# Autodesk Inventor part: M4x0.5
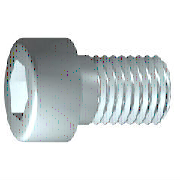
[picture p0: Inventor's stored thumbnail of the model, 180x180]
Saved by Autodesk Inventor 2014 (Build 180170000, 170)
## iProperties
IsCustomPart: 1
Company: 한국ATC센터
Created: 2009-02
Part Number: M4x0.5
Material: Steel, Mild
Description: 6각머리 태핑 나사
Document SubType Name: Modeling
Standard: KS B 1003
Designer: KYOUNG IL JANG
Standards Organization: KS
Language: ko-KR
Size Designation: M 4 x 12
Categories: <MemberInstance><Categories><Category DisplayName="조임쇠" InternalName="e4da775c-781d-43d5-af7c-5136215cf5a6" Mnemonic="FSTN"><Category DisplayName="볼트" InternalN
Density: 1 g/cm^3
Appearance: Steel
Author: KYOUNG IL JANG
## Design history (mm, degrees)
revolve "본체" stored, may be unused: angle "d10" = 90 deg
sketch "스케치2"
  geometry: L1 (0, -4.9)-(0, 4.9) reference; L2 (-4.9, 0)-(4.9, 0) reference; L3 (1.732, 0)-(0.866, -1.5); L4 (0.866, -1.5)-(-0.866, -1.5); L5 (-0.866, -1.5)-(-1.732, 0); L6 (-1.732, 0)-(-0.866, 1.5); L7 (-0.866, 1.5)-(0.866, 1.5); L8 (0.866, 1.5)-(1.732, 0); 2 further points
  constraints: 12 end point, 1 coincident, 1 horizontal alignment, 1 point on line, 12 other
extrude "슬롯" join sketch "스케치2" stored distance "d11" = 10; taper "d12" = 0 deg
workplane "Work Plane1"
fillet "Fillet2" dims "d30" = 0.1 (= R)
body "Solid1"
fillet "모깎기1" dims "d17" = 0.4 (= RR)
feature "스레드" dims "d13" = 10.25 (= GEL), "d14" = 0
chamfer "모따기1" distance "d15" = 0.42941 (= -0.5 x SPD + 0.5 x GD); stored, may be unused: second distance "d16" = 0.42941 (= GUL), angle "d27" = 45 deg
sketch "스케치1"
  geometry: L1 (-1, 0)-(12, 0); L2 (12, 0)-(12, 2); L3 (12, 2)-(1.75, 2); L4 (1.75, 2)-(1.32, 2); L5 (1.32, 2)-(0, 2); L6 (0, 2)-(0, 3.5); L7 (0, 3.5)-(-4, 3.5); L8 (-4, 3.5)-(-4, 1.732); L9 (-4, 1.732)-(-2, 1.732); L10 (-2, 1.732)-(-1, 0); L11 (-7.2, 0)-(15.2, 0) reference; L12 (0, -0.7)-(0, 4.2) reference; L13 (1.75, 2)-(0, 2)
  constraints: 22 end point, 6 parallel, 2 collinear, 2 perpendicular, 1 horizontal, 1 point on line
  dimensions: "d1" = 10.25 distance from line of L3.end L2 (= GEL); "d2" = 0.42952 distance of L4.end L3.end (computed from GAL); "d3" = 4 distance between parallel lines of L8 L6 (= KOH); "d4" = 2 distance of L8.end L9.end (= INTI); "d5" = 60 deg angle of L10 L1; "d6" = 4 diameter of L3 L1 (= GD); "d7" = 4 diameter of L5 L1 (= BDM); "d8" = 3.4641 diameter of L9 L1 (= 1.1547 x SW); "d9" = 7 diameter of L7 L1 (= KOD); "d26" = 12 distance between parallel lines of L12 L2 (= NLG)
other parameters: "GD" = 4 (= NND) [user parameter; used in 2 equation terms], "NLG" = 12 [user parameter; used in 1 equation term], "GEL" = 10.25 [user parameter; used in 2 equation terms], "KOD" = 7 [user parameter; used in 1 equation term], "KOH" = 4 [user parameter; used in 1 equation term], "INTI" = 2 [user parameter; used in 1 equation term], "GAL" = 0.42941 (= 0.61345 x PTC) [user parameter; used in 1 equation term], "GUL" = 0.42941 (= 0.61345 x PTC) [user parameter; used in 1 equation term], "BDM" = 4 (= NND) [user parameter; used in 1 equation term], "SW" = 3 [user parameter; used in 2 equation terms], "RR" = 0.4 [user parameter; used in 1 equation term], "SPD" = 3.14117 (= NND - 1.2269 x PTC) [user parameter; used in 1 equation term], "d19" = 0, "d28" = 0, "d29" = 0, "R" = 0.1 [user parameter; used in 1 equation term], "PHH" = 0.2 [user parameter], "GD1" = 3.14117 (= THREADDIA - 1.2269 x PTC) [user parameter], "THREADDIA" = 4 [user parameter; used in 1 equation term], "FAWI" = 45 deg [user parameter], "TPU" = 14.28571 (computed from PTC) [user parameter], "PTC" = 0.7 [user parameter; used in 5 equation terms], "NND" = 4 [user parameter; used in 3 equation terms], "TOA" = 30 deg [user parameter], "E0" = 3.465 (= 1.155 x SW) [user parameter]
